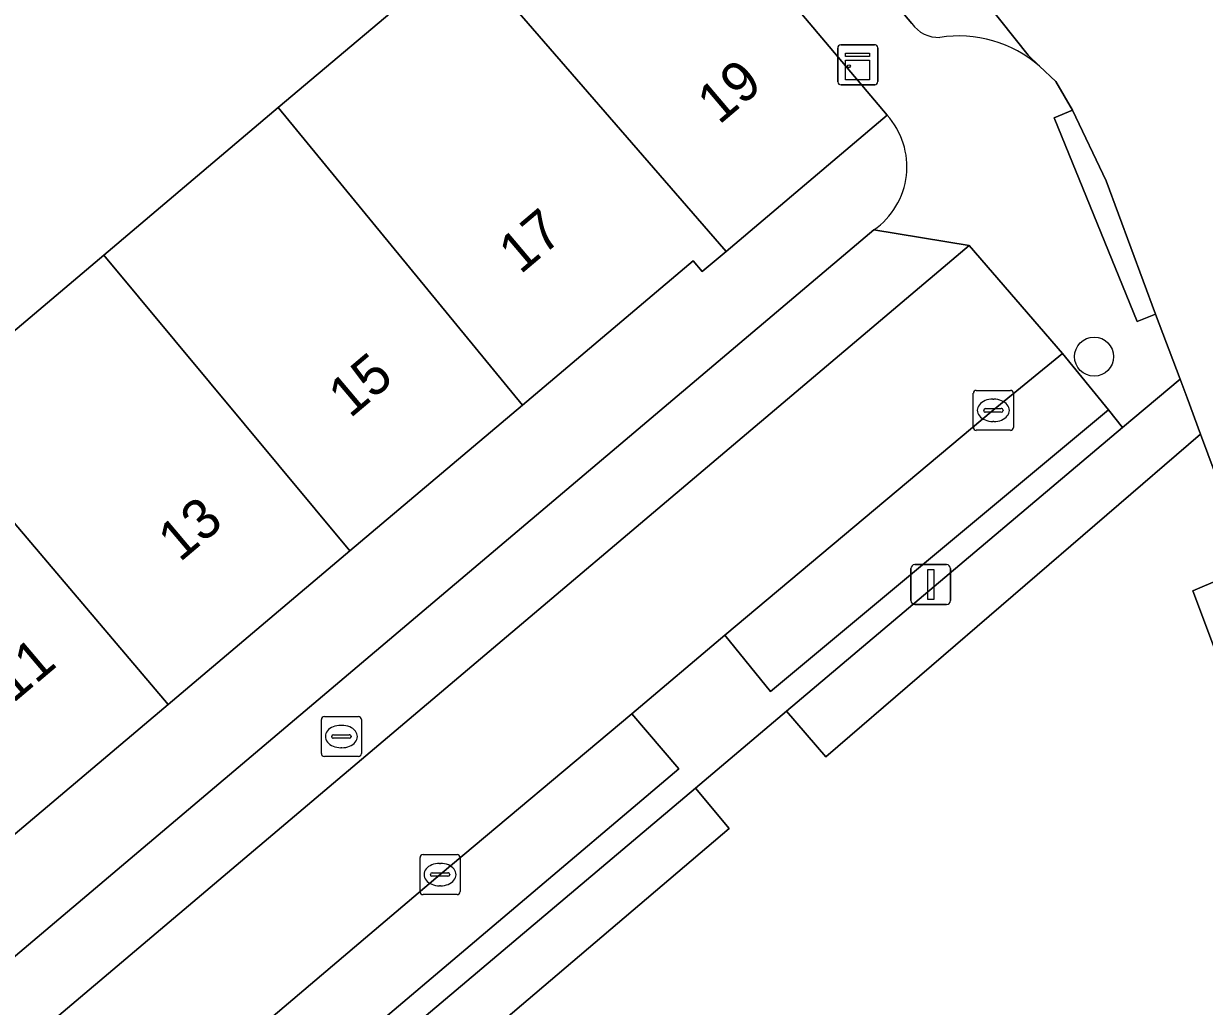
# Model space of a CAD drawing. Extents: x 162172 to 163187, y 382874 to 383685.
# Drawn here: x 162318.4 to 162347.93, y 383156.85 to 383181.44 of the extents above; entities that cross this region are included whole.
import ezdxf

# ---------------------------------------------------------------- set-up
doc = ezdxf.new("R2010")
doc.units = 0
for name, color, linetype in [('IMGEO_Boom', 7, 'Continuous'), ('IMGEO_Brandkraan', 7, 'Continuous'), ('IMGEO_Erf', 7, 'Continuous'), ('IMGEO_Groenvoorziening', 7, 'Continuous'), ('IMGEO_Haag', 7, 'Continuous'), ('IMGEO_Kast', 7, 'Continuous'), ('IMGEO_Kolk', 7, 'Continuous'), ('IMGEO_Lichtmast', 7, 'Continuous'), ('IMGEO_Pand', 7, 'Continuous'), ('IMGEO_Pand_nummerreeks', 7, 'Continuous'), ('IMGEO_Parkeervlak_open', 7, 'Continuous'), ('IMGEO_Rijbaan_lokaal_open', 7, 'Continuous'), ('IMGEO_Voetpad_open', 7, 'Continuous')]:
    doc.layers.add(name, color=color, linetype=linetype)

msp = doc.modelspace()

# ---------------------------------------------------------------- linework, layer by layer
at = {"layer": 'IMGEO_Boom'}
msp.add_circle((162345.175, 383173.105), 0.489, dxfattribs=at)
at = {"layer": 'IMGEO_Brandkraan'}
for p, q in [((162325.847, 383163.174), (162325.847, 383164.026)), ((162325.922, 383164.1), (162326.774, 383164.1)), ((162326.335, 383163.88), (162326.36, 383163.88)), ((162326.848, 383164.026), (162326.848, 383163.174)), ((162326.106, 383163.594), (162326.106, 383163.606)), ((162326.544, 383163.557), (162326.146, 383163.557)), ((162326.149, 383163.643), (162326.547, 383163.643)), ((162326.59, 383163.606), (162326.59, 383163.594)), ((162326.358, 383163.32), (162326.333, 383163.32)), ((162326.774, 383163.1), (162325.922, 383163.1))]:
    msp.add_line(p, q, dxfattribs=at)
for points in [[(162325.847, 383163.174), (162325.847, 383164.026)], [(162325.922, 383164.1), (162326.774, 383164.1)], [(162326.848, 383164.026), (162326.848, 383163.174)], [(162326.774, 383163.1), (162325.922, 383163.1)]]:
    msp.add_lwpolyline(points, dxfattribs=at)
for centre, radius, start, end in [((162325.924, 383164.024), 0.0765, 91.552, 178.448), ((162325.924, 383164.024), 0.0765, 91.552, 178.448), ((162326.772, 383164.024), 0.0765, 1.552, 88.448), ((162326.772, 383164.024), 0.0765, 1.552, 88.448), ((162326.146, 383163.603), 0.0403, 85.8775, 175.7526), ((162326.143, 383163.593), 0.0366, 178.938, 274.7102), ((162326.547, 383163.6), 0.043, 264.8664, 352.4533), ((162326.551, 383163.605), 0.0386, 1.7309, 96.639), ((162325.924, 383163.176), 0.0765, 181.552, 268.448), ((162325.924, 383163.176), 0.0765, 181.552, 268.448), ((162326.772, 383163.176), 0.0765, 271.552, 358.448), ((162326.772, 383163.176), 0.0765, 271.552, 358.448)]:
    msp.add_arc(centre, radius, start, end, dxfattribs=at)
for centre, major_axis, ratio, start_param, end_param in [((162326.334, 383163.6), (-0.387, 0.002), 0.722429, 4.712389, 7.853982), ((162326.359, 383163.6), (-0.39, 0.002), 0.717154, 1.570796, 4.712389)]:
    msp.add_ellipse(centre, major_axis=major_axis, ratio=ratio, start_param=start_param, end_param=end_param, dxfattribs=at)
at = {"layer": 'IMGEO_Erf'}
for points in [[(162298.744, 383157.331), (162299.171, 383157.692), (162303.063, 383160.983), (162307.191, 383164.472), (162311.64, 383168.234), (162315.788, 383171.741), (162320.403, 383175.643), (162324.77, 383179.335), (162328.927, 383182.849)], [(162339.995, 383179.146), (162335.969, 383175.736), (162335.373, 383175.231), (162335.143, 383175.498), (162330.88, 383171.894), (162326.561, 383168.244), (162322.016, 383164.402), (162317.811, 383160.846), (162313.413, 383157.129), (162309.316, 383153.666), (162305.323, 383150.29), (162304.962, 383149.985), (162305.184, 383149.712), (162300.554, 383145.796)], [(162303.372, 383145.574), (162339.665, 383176.277)]]:
    msp.add_lwpolyline(points, dxfattribs=at)
msp.add_arc((162338.572, 383177.856), 1.921, 304.6881, 42.189, dxfattribs=at)
at = {"layer": 'IMGEO_Groenvoorziening'}
for points in [[(162347.838, 383171.163), (162347.5, 383172.071), (162347.325, 383172.541), (162345.888, 383171.328), (162337.483, 383164.232), (162338.468, 383163.089)], [(162360.369, 383137.577), (162355.914, 383149.578), (162350.1, 383165.084), (162349.07, 383167.852), (162347.643, 383167.248), (162358.978, 383137.041)], [(162318.422, 383148.141), (162319.29, 383147.041), (162336.048, 383161.296), (162335.202, 383162.307)]]:
    msp.add_lwpolyline(points, close=True, dxfattribs=at)
for points in [[(162347.838, 383171.163), (162338.468, 383163.089), (162337.483, 383164.232)], [(162349.07, 383167.852), (162347.838, 383171.163)], [(162360.369, 383137.577), (162358.978, 383137.041), (162347.643, 383167.248), (162349.07, 383167.852)], [(162337.483, 383164.232), (162335.202, 383162.307)], [(162335.202, 383162.307), (162336.048, 383161.296), (162319.29, 383147.041), (162318.422, 383148.141)]]:
    msp.add_lwpolyline(points, dxfattribs=at)
at = {"layer": 'IMGEO_Haag'}
for points in [[(162347.838, 383171.163), (162347.5, 383172.071), (162347.325, 383172.541), (162345.888, 383171.328), (162337.483, 383164.232), (162338.468, 383163.089)], [(162360.369, 383137.577), (162355.914, 383149.578), (162350.1, 383165.084), (162349.07, 383167.852), (162347.643, 383167.248), (162358.978, 383137.041)], [(162318.422, 383148.141), (162319.29, 383147.041), (162336.048, 383161.296), (162335.202, 383162.307)]]:
    msp.add_lwpolyline(points, close=True, dxfattribs=at)
at = {"layer": 'IMGEO_Kast'}
for p, q in [((162338.763, 383179.981), (162338.763, 383180.822)), ((162338.763, 383180.822), (162338.763, 383179.981)), ((162338.838, 383180.906), (162339.679, 383180.906)), ((162339.679, 383180.906), (162338.838, 383180.906)), ((162339.763, 383180.831), (162339.763, 383179.99)), ((162339.763, 383179.99), (162339.763, 383180.831)), ((162339.688, 383179.906), (162338.847, 383179.906)), ((162338.847, 383179.906), (162339.688, 383179.906))]:
    msp.add_line(p, q, dxfattribs=at)
for points in [[(162338.958, 383180.696), (162339.558, 383180.696), (162339.558, 383180.611), (162338.958, 383180.611), (162338.958, 383180.696)], [(162338.958, 383180.521), (162339.558, 383180.521), (162339.558, 383180.032), (162338.958, 383180.032), (162338.958, 383180.521)]]:
    msp.add_lwpolyline(points, dxfattribs=at)
msp.add_circle((162339.042, 383180.37), 0.0377, dxfattribs=at)
for centre, start, end in [((162338.841, 383180.828), 92.4484, 184.2845), ((162338.841, 383180.828), 92.4484, 184.2845), ((162339.685, 383180.828), 2.4484, 94.2845), ((162339.685, 383180.828), 2.4484, 94.2845), ((162338.841, 383179.984), 182.4484, 274.2845), ((162338.841, 383179.984), 182.4484, 274.2845), ((162339.685, 383179.984), 272.4484, 4.2845), ((162339.685, 383179.984), 272.4484, 4.2845)]:
    msp.add_arc(centre, 0.0779, start, end, dxfattribs=at)
at = {"layer": 'IMGEO_Kolk'}
for p, q in [((162342.154, 383171.335), (162342.154, 383172.187)), ((162342.229, 383172.261), (162343.081, 383172.261)), ((162343.155, 383172.187), (162343.155, 383171.335)), ((162342.456, 383171.804), (162342.854, 383171.804)), ((162342.642, 383172.041), (162342.667, 383172.041)), ((162342.413, 383171.755), (162342.413, 383171.767)), ((162342.851, 383171.718), (162342.453, 383171.718)), ((162342.897, 383171.767), (162342.897, 383171.755)), ((162343.081, 383171.261), (162342.229, 383171.261)), ((162342.665, 383171.481), (162342.64, 383171.481)), ((162328.39, 383160.645), (162329.242, 383160.645)), ((162328.315, 383159.719), (162328.315, 383160.571)), ((162328.803, 383160.425), (162328.828, 383160.425)), ((162329.316, 383160.571), (162329.316, 383159.719)), ((162328.574, 383160.139), (162328.574, 383160.151)), ((162329.012, 383160.102), (162328.614, 383160.102)), ((162328.617, 383160.188), (162329.015, 383160.188)), ((162329.058, 383160.151), (162329.058, 383160.139)), ((162328.826, 383159.865), (162328.801, 383159.865)), ((162329.242, 383159.645), (162328.39, 383159.645))]:
    msp.add_line(p, q, dxfattribs=at)
for points in [[(162342.154, 383171.335), (162342.154, 383172.187)], [(162342.229, 383172.261), (162343.081, 383172.261)], [(162343.155, 383172.187), (162343.155, 383171.335)], [(162343.081, 383171.261), (162342.229, 383171.261)], [(162328.39, 383160.645), (162329.242, 383160.645)], [(162328.315, 383159.719), (162328.315, 383160.571)], [(162329.316, 383160.571), (162329.316, 383159.719)], [(162329.242, 383159.645), (162328.39, 383159.645)]]:
    msp.add_lwpolyline(points, dxfattribs=at)
for centre, radius, start, end in [((162342.231, 383172.185), 0.0765, 91.552, 178.448), ((162342.231, 383172.185), 0.0765, 91.552, 178.448), ((162343.079, 383172.185), 0.0765, 1.552, 88.448), ((162343.079, 383172.185), 0.0765, 1.552, 88.448), ((162342.453, 383171.764), 0.0403, 85.8775, 175.7526), ((162342.858, 383171.766), 0.0386, 1.7309, 96.639), ((162342.45, 383171.754), 0.0366, 178.938, 274.7102), ((162342.854, 383171.761), 0.043, 264.8664, 352.4533), ((162342.231, 383171.337), 0.0765, 181.552, 268.448), ((162342.231, 383171.337), 0.0765, 181.552, 268.448), ((162343.079, 383171.337), 0.0765, 271.552, 358.448), ((162343.079, 383171.337), 0.0765, 271.552, 358.448), ((162328.392, 383160.569), 0.0765, 91.552, 178.448), ((162328.392, 383160.569), 0.0765, 91.552, 178.448), ((162329.24, 383160.569), 0.0765, 1.552, 88.448), ((162329.24, 383160.569), 0.0765, 1.552, 88.448), ((162328.614, 383160.148), 0.0403, 85.8775, 175.7526), ((162328.611, 383160.138), 0.0366, 178.938, 274.7102), ((162329.015, 383160.145), 0.043, 264.8664, 352.4533), ((162329.019, 383160.15), 0.0386, 1.7309, 96.639), ((162328.392, 383159.721), 0.0765, 181.552, 268.448), ((162328.392, 383159.721), 0.0765, 181.552, 268.448), ((162329.24, 383159.721), 0.0765, 271.552, 358.448), ((162329.24, 383159.721), 0.0765, 271.552, 358.448)]:
    msp.add_arc(centre, radius, start, end, dxfattribs=at)
for centre, major_axis, ratio, start_param, end_param in [((162342.641, 383171.761), (-0.387, 0.002), 0.722429, 4.712389, 7.853982), ((162342.666, 383171.761), (-0.39, 0.002), 0.717154, 1.570796, 4.712389), ((162328.802, 383160.145), (-0.387, 0.002), 0.722429, 4.712389, 7.853982), ((162328.827, 383160.145), (-0.39, 0.002), 0.717154, 1.570796, 4.712389)]:
    msp.add_ellipse(centre, major_axis=major_axis, ratio=ratio, start_param=start_param, end_param=end_param, dxfattribs=at)
at = {"layer": 'IMGEO_Lichtmast'}
for p, q in [((162340.592, 383167.002), (162340.592, 383167.802)), ((162340.592, 383167.802), (162340.592, 383167.002)), ((162340.692, 383167.902), (162341.482, 383167.902)), ((162341.482, 383167.902), (162340.692, 383167.902)), ((162341.582, 383167.802), (162341.582, 383167.002)), ((162341.582, 383167.002), (162341.582, 383167.802)), ((162341.482, 383166.902), (162340.692, 383166.902)), ((162340.692, 383166.902), (162341.482, 383166.902))]:
    msp.add_line(p, q, dxfattribs=at)
msp.add_lwpolyline([(162341.012, 383167.777), (162341.162, 383167.777), (162341.162, 383167.027), (162341.012, 383167.027), (162341.012, 383167.777)], dxfattribs=at)
for centre, start, end in [((162340.692, 383167.802), 90, 180), ((162340.692, 383167.802), 90, 180), ((162341.482, 383167.802), 0, 90), ((162341.482, 383167.802), 360, 90), ((162340.692, 383167.002), 180, 270), ((162340.692, 383167.002), 180, 270), ((162341.482, 383167.002), 270, 0), ((162341.482, 383167.002), 270, 0)]:
    msp.add_arc(centre, 0.1, start, end, dxfattribs=at)
at = {"layer": 'IMGEO_Pand'}
for points in [[(162335.969, 383175.736), (162339.995, 383179.146), (162336.823, 383182.913), (162333.317, 383187.038), (162329.205, 383183.544)], [(162335.969, 383175.736), (162329.205, 383183.544), (162328.7, 383183.115), (162328.927, 383182.849), (162324.77, 383179.335), (162330.88, 383171.894), (162335.143, 383175.498), (162335.373, 383175.231)], [(162330.88, 383171.894), (162324.77, 383179.335), (162320.403, 383175.643), (162326.561, 383168.244)], [(162322.016, 383164.402), (162326.561, 383168.244), (162320.403, 383175.643), (162315.788, 383171.741)], [(162322.016, 383164.402), (162315.788, 383171.741), (162311.64, 383168.234), (162317.811, 383160.846)]]:
    msp.add_lwpolyline(points, close=True, dxfattribs=at)
at = {"layer": 'IMGEO_Parkeervlak_open'}
for points in [[(162343.809, 383180.374), (162343.522, 383180.645), (162341.765, 383182.865), (162330.343, 383196.409), (162318.375, 383210.519), (162317.277, 383211.765), (162316.532, 383212.648), (162316.128, 383213.123)], [(162316.591, 383209.812), (162317.886, 383208.278), (162340.616, 383181.437)]]:
    msp.add_lwpolyline(points, dxfattribs=at)
for points in [[(162344.383, 383173.184), (162342.654, 383171.762), (162335.935, 383166.133), (162337.082, 383164.723), (162345.536, 383171.775)], [(162316.419, 383149.634), (162317.605, 383148.249), (162334.784, 383162.792), (162333.613, 383164.164), (162328.815, 383160.146), (162319.473, 383152.215)]]:
    msp.add_lwpolyline(points, close=True, dxfattribs=at)
for centre, radius, start, end in [((162341.279, 383181.901), 0.809, 215.0154, 272.6429), ((162341.786, 383178.042), 3.087, 49.0658, 98.7583)]:
    msp.add_arc(centre, radius, start, end, dxfattribs=at)
at = {"layer": 'IMGEO_Rijbaan_lokaal_open'}
msp.add_lwpolyline([(162316.128, 383213.123), (162316.532, 383212.648), (162317.277, 383211.765), (162318.375, 383210.519), (162330.343, 383196.409), (162341.765, 383182.865), (162343.522, 383180.645), (162343.809, 383180.374), (162344.215, 383179.988), (162344.636, 383179.27), (162345.477, 383177.503), (162346.713, 383174.171), (162347.325, 383172.541), (162347.5, 383172.071), (162347.838, 383171.163), (162349.07, 383167.852), (162350.1, 383165.084), (162355.914, 383149.578), (162360.369, 383137.577), (162361.702, 383133.987), (162361.794, 383133.759)], dxfattribs=at)
msp.add_lwpolyline([(162333.613, 383164.164), (162335.935, 383166.133), (162342.654, 383171.762), (162344.383, 383173.184), (162342.05, 383175.889), (162304.504, 383144.126), (162303.781, 383143.539), (162306.044, 383140.853), (162306.524, 383141.258), (162307.054, 383141.705), (162314.114, 383147.678), (162316.419, 383149.634), (162319.473, 383152.215), (162328.815, 383160.146)], close=True, dxfattribs=at)
at = {"layer": 'IMGEO_Voetpad_open'}
for points in [[(162316.38, 383210.548), (162314.195, 383209.68), (162320.875, 383201.8), (162333.317, 383187.038), (162336.823, 383182.913), (162339.995, 383179.146)], [(162340.616, 383181.437), (162317.886, 383208.278), (162316.591, 383209.812)], [(162344.173, 383179.082), (162344.636, 383179.27), (162344.215, 383179.988), (162343.809, 383180.374)], [(162339.665, 383176.277), (162342.05, 383175.889), (162344.383, 383173.184), (162345.536, 383171.775), (162345.888, 383171.328), (162347.325, 383172.541), (162346.713, 383174.171), (162346.25, 383173.983), (162344.173, 383179.082)]]:
    msp.add_lwpolyline(points, dxfattribs=at)
for points in [[(162346.713, 383174.171), (162345.477, 383177.503), (162344.636, 383179.27), (162344.173, 383179.082), (162346.25, 383173.983)], [(162342.05, 383175.889), (162339.665, 383176.277), (162303.372, 383145.574), (162303.781, 383143.539), (162304.504, 383144.126)], [(162318.003, 383147.787), (162318.422, 383148.141), (162335.202, 383162.307), (162337.483, 383164.232), (162345.888, 383171.328), (162345.536, 383171.775), (162337.082, 383164.723), (162335.935, 383166.133), (162333.613, 383164.164), (162334.784, 383162.792), (162317.605, 383148.249), (162316.419, 383149.634), (162314.114, 383147.678), (162315.305, 383146.31), (162307.689, 383139.879), (162308.056, 383139.384), (162308.203, 383139.513), (162315.689, 383145.833), (162315.804, 383145.93)]]:
    msp.add_lwpolyline(points, close=True, dxfattribs=at)
for centre, radius, start, end in [((162341.279, 383181.901), 0.809, 215.0154, 272.6429), ((162341.786, 383178.042), 3.087, 49.0658, 98.7583), ((162338.572, 383177.856), 1.921, 304.6881, 42.189)]:
    msp.add_arc(centre, radius, start, end, dxfattribs=at)

# ---------------------------------------------------------------- texts
at = {"layer": 'IMGEO_Pand_nummerreeks'}
for s, rotation, p in [('19', 40.2644, (162335.793, 383178.889)), ('17', 40.2091, (162330.825, 383175.147)), ('15', 40.2091, (162326.565, 383171.546)), ('13', 40.2091, (162322.305, 383167.945)), ('11', 40.2091, (162318.132, 383164.418))]:
    msp.add_text(s, height=1, rotation=rotation, dxfattribs=at).set_placement(p)

doc.saveas('drawing.dxf')
